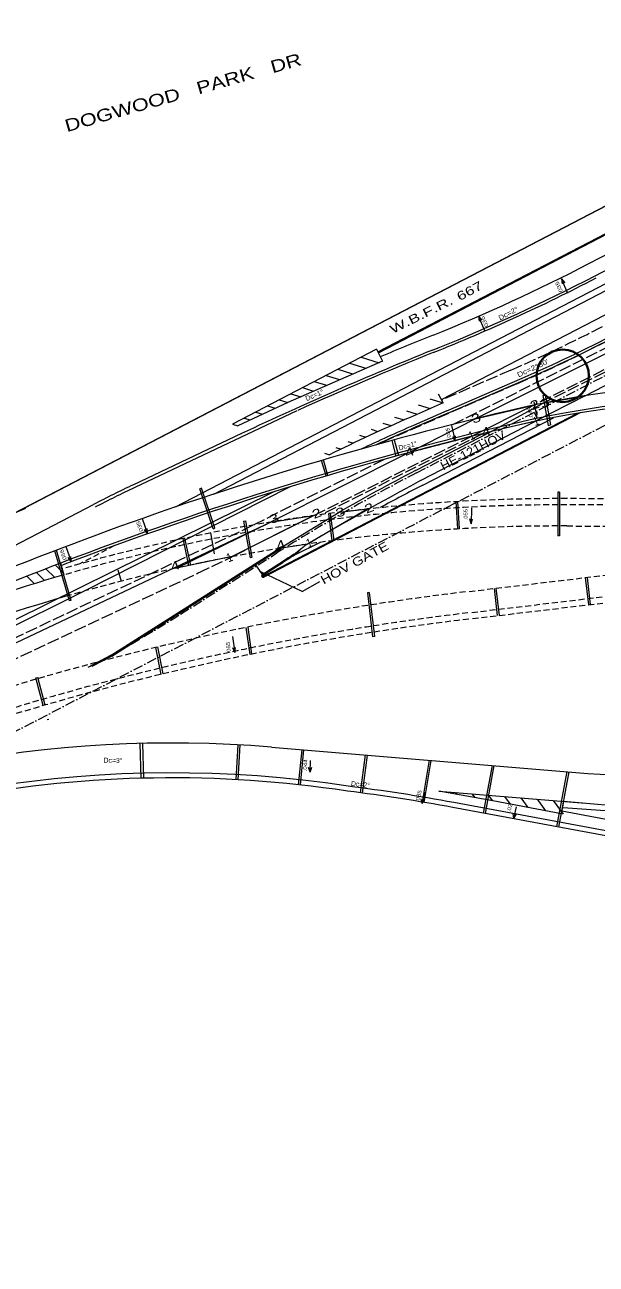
# Model space of a CAD drawing. Extents: x 2354993 to 2372084, y 6966390 to 6990057.
# Drawn here: x 2362087 to 2363006, y 6976825 to 6978818 of the extents above; entities that cross this region are included whole.
import ezdxf
from ezdxf.enums import TextEntityAlignment as Align

# ---------------------------------------------------------------- set-up
doc = ezdxf.new("R2010")
doc.units = 0
doc.header["$LTSCALE"] = 3.2
for name, pattern in [('DOT_DASHED', [7.7, 5, -1.2, 0.3, -1.2]), ('LONG_DASHED', [7.5, 6, -1.5]), ('MEDIUM_DASHED', [4.5, 3, -1.5])]:
    doc.linetypes.add(name, pattern=pattern)
for name, color, linetype, lineweight in [('1', 7, 'Continuous', 35), ('12', 7, 'Continuous', 13), ('13', 7, 'Continuous', 13), ('17', 7, 'Continuous', 13), ('19', 7, 'Continuous', 13), ('25', 7, 'Continuous', 13), ('4', 7, 'Continuous', 13), ('5', 7, 'Continuous', 13), ('6', 7, 'Continuous', 13), ('61', 7, 'Continuous', 13), ('63', 7, 'Continuous', 13), ('9', 7, 'Continuous', 13)]:
    doc.layers.add(name, color=color, linetype=linetype, lineweight=lineweight)

msp = doc.modelspace()

# ---------------------------------------------------------------- linework, layer by layer
at = {"layer": '1', "lineweight": 40}
msp.add_circle((2362951.982, 6978253.986), 42.179, dxfattribs=at)
at = {"layer": '12'}
for p, q in [((2362571.803, 6978092.884), (2362564.446, 6978117.821)), ((2362574.682, 6978093.733), (2362567.324, 6978118.67)), ((2362371.377, 6978073.296), (2362368.532, 6978072.348)), ((2362390.025, 6978007.891), (2362368.532, 6978072.348)), ((2362392.719, 6978009.291), (2362371.377, 6978073.296)), ((2362946.885, 6978066.796), (2362943.878, 6978066.795)), ((2362943.885, 6978066.795), (2362943.935, 6977996.56)), ((2362946.885, 6978066.796), (2362946.934, 6977996.561)), ((2362780.042, 6978051.58), (2362782.606, 6978007.655)), ((2362783.038, 6978051.756), (2362785.602, 6978007.831)), ((2362439.038, 6978020.407), (2362441.991, 6978020.93)), ((2362439.038, 6978020.407), (2362449.499, 6977961.336)), ((2362441.991, 6978020.93), (2362452.451, 6977961.859)), ((2362575.239, 6978032.315), (2362580.866, 6977988.676)), ((2362578.214, 6978032.698), (2362583.841, 6977989.06)), ((2362389.745, 6978018.211), (2362386.9, 6978017.263)), ((2362341.312, 6977992.101), (2362350.49, 6977949.069)), ((2362344.245, 6977992.726), (2362353.424, 6977949.694)), ((2362946.949, 6977996.561), (2362943.935, 6977996.56)), ((2362159.001, 6977891.989), (2362135.767, 6977972.726)), ((2362161.883, 6977892.818), (2362138.577, 6977973.802)), ((2362452.451, 6977961.859), (2362449.499, 6977961.336)), ((2362161.883, 6977892.818), (2362159.001, 6977891.989)), ((2362105.187, 6977768.143), (2362108.085, 6977768.92)), ((2362117.11, 6977723.657), (2362105.187, 6977768.143)), ((2362119.992, 6977724.493), (2362108.085, 6977768.92)), ((2362126.194, 6977701.35), (2362123.296, 6977700.573)), ((2362272.444, 6977662.559), (2362274.102, 6977606.792)), ((2362276.443, 6977662.678), (2362278.1, 6977606.896))]:
    msp.add_line(p, q, dxfattribs=at)
for points in [[(2362640.897, 6977905.496), (2362637.913, 6977905.14), (2362646.394, 6977834.183)], [(2362640.897, 6977905.496), (2362649.372, 6977834.54), (2362646.391, 6977834.183)]]:
    msp.add_lwpolyline(points, dxfattribs=at)
at = {"layer": '17'}
for p, q in [((2362919.834, 6978222.065), (2362923.771, 6978222.772)), ((2362919.834, 6978222.065), (2362928.413, 6978174.288)), ((2362923.771, 6978222.772), (2362932.35, 6978174.995)), ((2362928.413, 6978174.288), (2362932.35, 6978174.995)), ((2362677.146, 6978149.827), (2362683.958, 6978124.875)), ((2362681.005, 6978150.881), (2362687.817, 6978125.928)), ((2361706.685, 6977651.285), (2362482.125, 6978018.666)), ((2362546.028, 6977616.636), (2362543.26, 6977624.219)), ((2362546.028, 6977616.636), (2362546.795, 6977635.37)), ((2362546.028, 6977616.636), (2362548.839, 6977624.427)), ((2362726.084, 6977566.046), (2362730.092, 6977584.363)), ((2362726.084, 6977566.046), (2362724.675, 6977573.994)), ((2362726.084, 6977566.046), (2362730.206, 6977573.23)), ((2362873.476, 6977542.3), (2362872.067, 6977550.248)), ((2362873.476, 6977542.299), (2362877.484, 6977560.616)), ((2362873.476, 6977542.3), (2362877.598, 6977549.484))]:
    msp.add_line(p, q, dxfattribs=at)
at = {"layer": '19'}
for p, q in [((2362949.899, 6978409.967), (2362951.045, 6978401.741)), ((2362949.899, 6978409.967), (2362955.212, 6978403.576)), ((2362960.316, 6978386.382), (2362949.899, 6978409.967)), ((2362816.435, 6978349.953), (2362817.581, 6978341.727)), ((2362816.435, 6978349.953), (2362821.748, 6978343.562)), ((2362826.852, 6978326.368), (2362816.435, 6978349.953)), ((2362905.52, 6978212.363), (2362910.407, 6978187.048)), ((2362910.407, 6978187.048), (2362906.655, 6978194.465)), ((2362910.407, 6978187.048), (2362911.126, 6978195.322)), ((2362779.224, 6978148.867), (2362775.199, 6978155.884)), ((2362804.585, 6978016.032), (2362802.457, 6978024.066)), ((2362284.473, 6977999.932), (2362279.726, 6978006.753)), ((2362161.719, 6977955.18), (2362156.972, 6977962.001)), ((2362424.912, 6977809.025), (2362421.526, 6977816.614))]:
    msp.add_line(p, q, dxfattribs=at)
for points in [[(2362773.018, 6978173.891), (2362779.224, 6978148.867), (2362779.509, 6978157.168)], [(2362805.067, 6978041.81), (2362804.585, 6978016.032), (2362807.009, 6978023.976)], [(2362276.11, 6978024.32), (2362284.473, 6977999.932), (2362284.034, 6978008.226)], [(2362153.356, 6977979.568), (2362161.719, 6977955.18), (2362161.28, 6977963.474)], [(2362421.264, 6977834.548), (2362424.912, 6977809.025), (2362426.034, 6977817.254)]]:
    msp.add_lwpolyline(points, dxfattribs=at)
at = {"layer": '25'}
for p, q in [((2358006.591, 6975920.846), (2363488.891, 6978770.331)), ((2362811.106, 6978184.667), (2363604.71, 6978582.7)), ((2363003.914, 6978414.83), (2363230.047, 6978532.352)), ((2362988.207, 6978222.005), (2363089.737, 6978274.358)), ((2362759.919, 6978210.266), (2362752.541, 6978224.463)), ((2362975.243, 6978193.546), (2362580.871, 6977988.675)), ((2362980.038, 6978194.347), (2362692.88, 6978045.172)), ((2362723.338, 6978085.426), (2362908.292, 6978180.797)), ((2362704.108, 6978130.197), (2362482.125, 6978018.666)), ((2362692.88, 6978045.172), (2362471.439, 6977930.136)), ((2362580.871, 6977988.675), (2362470.748, 6977931.467)), ((2362226.42, 6977804.541), (2362490.493, 6977972.46)), ((2362227.174, 6977803.242), (2362491.298, 6977971.194)), ((2362457.957, 6977949.993), (2362468.945, 6977934.464)), ((2362468.945, 6977934.464), (2362501.492, 6977955.16)), ((2362469.73, 6977933.185), (2362502.297, 6977953.894)), ((2362532.928, 6977907.156), (2362465.571, 6977939.397)), ((2362532.928, 6977907.156), (2362561.479, 6977922.997))]:
    msp.add_line(p, q, dxfattribs=at)
at = {"layer": '25', "linetype": 'LONG_DASHED'}
for p, q in [((2362775.435, 6978175.726), (2363601.123, 6978589.851)), ((2363618.55, 6978565.019), (2362905.562, 6978206.794)), ((2363084.717, 6978292.33), (2362920.65, 6978209.898)), ((2362868.725, 6978263.158), (2362757.536, 6978214.854)), ((2362878.281, 6978241.142), (2362652.39, 6978143.01)), ((2362822.936, 6978160.805), (2362564.328, 6978030.873)), ((2362805.354, 6978156.448), (2362420.606, 6977963.184)), ((2362665.112, 6978119.556), (2362455.357, 6978014.169)), ((2361699.088, 6977656.554), (2362455.357, 6978014.169)), ((2361711.836, 6977629.398), (2362366.21, 6977936.92))]:
    msp.add_line(p, q, dxfattribs=at)
at = {"layer": '25', "linetype": 'MEDIUM_DASHED'}
msp.add_line((2362231.704, 6977980.832), (2362174.616, 6977951.163), dxfattribs=at)
at = {"layer": '25', "linetype": 'LONG_DASHED'}
for centre, radius, start, end in [((2361957.93, 6980359.697), 2285.831, 293.48147, 297.64944), ((2361957.927, 6980359.696), 2309.831, 293.48137, 297.6495), ((2361144.348, 6980536.913), 2872.789, 295.17109, 296.37586)]:
    msp.add_arc(centre, radius, start, end, dxfattribs=at)
at = {"layer": '25'}
for centre, radius, start, end in [((2365652.69, 6972668.039), 6158.667, 118.40149, 120.33806), ((2364029.86, 6975551.655), 2850.789, 121.46196, 121.59891), ((2364029.86, 6975551.655), 2868.789, 122.30227, 122.45191), ((2364029.86, 6975551.655), 2867.289, 122.23233, 122.45191), ((2364029.86, 6975551.655), 2848.289, 122.00852, 122.45191), ((2364029.86, 6975551.655), 2846.789, 122.01179, 122.45191), ((2362470.287, 6977932.355), 2.5, 122.45143, 297.45154), ((2362470.287, 6977932.355), 1, 122.45143, 297.45154)]:
    msp.add_arc(centre, radius, start, end, dxfattribs=at)
at = {"layer": '4'}
for p, q in [((2362757.154, 6978215.587), (2363268.695, 6978481.438)), ((2362385.833, 6978001.212), (2362391.796, 6977967.815)), ((2362520.138, 6977966.916), (2362536.133, 6977979.777)), ((2362520.795, 6977965.558), (2362536.133, 6977979.777)), ((2362242.862, 6977923.152), (2362237.538, 6977941.259))]:
    msp.add_line(p, q, dxfattribs=at)
at = {"layer": '5'}
for p, q in [((2362087.371, 6978041.876), (2363419.143, 6978734.078)), ((2362654.988, 6978292.473), (2363507.292, 6978735.395)), ((2362655.626, 6978291.114), (2363508.018, 6978734.082)), ((2362391.142, 6978063.692), (2363583.984, 6978683.611)), ((2362993.757, 6978434.346), (2363229.499, 6978556.861)), ((2362329.78, 6978043.07), (2363248.405, 6978520.479)), ((2362742.392, 6978295.091), (2362751.833, 6978298.893)), ((2362652.848, 6978297.032), (2362421.419, 6978176.314)), ((2362627.951, 6978284.047), (2362656.76, 6978274.985)), ((2362652.848, 6978297.032), (2362662.138, 6978277.243)), ((2362590.336, 6978264.425), (2362614.259, 6978256.904)), ((2362609.144, 6978274.236), (2362635.439, 6978265.969)), ((2362552.719, 6978244.803), (2362572.28, 6978238.654)), ((2362571.528, 6978254.614), (2362593.203, 6978247.8)), ((2362765.497, 6978197.425), (2362886.96, 6978250.192)), ((2362767.091, 6978193.757), (2362888.554, 6978246.524)), ((2362515.102, 6978225.182), (2362530.824, 6978220.239)), ((2362533.911, 6978234.992), (2362551.488, 6978229.467)), ((2362477.487, 6978205.559), (2362489.88, 6978201.664)), ((2362496.294, 6978215.371), (2362510.289, 6978210.971)), ((2362759.919, 6978210.266), (2362706.512, 6978187.064)), ((2362719.45, 6978207.266), (2362738.922, 6978201.144)), ((2362738.3, 6978217.063), (2362759.919, 6978210.266)), ((2362524.395, 6978197.427), (2362264.183, 6978074.352)), ((2362439.869, 6978185.939), (2362449.429, 6978182.933)), ((2362458.678, 6978195.749), (2362469.594, 6978192.317)), ((2362681.747, 6978187.672), (2362696.925, 6978182.899)), ((2362700.597, 6978197.468), (2362717.922, 6978192.021)), ((2362765.497, 6978197.425), (2362712.091, 6978174.224)), ((2362767.091, 6978193.756), (2362713.852, 6978170.627)), ((2362727.004, 6978078.316), (2362937.068, 6978186.635)), ((2362435.758, 6978161.035), (2362262.045, 6978078.872)), ((2362421.419, 6978176.314), (2362429.768, 6978173.689)), ((2362435.377, 6978160.855), (2362435.764, 6978161.038)), ((2362644.044, 6978168.078), (2362654.929, 6978164.655)), ((2362662.895, 6978177.874), (2362675.926, 6978173.777)), ((2362715.089, 6978101.424), (2362836.859, 6978164.214)), ((2362437.088, 6978157.239), (2362437.474, 6978157.422)), ((2362606.34, 6978148.483), (2362615.458, 6978145.615)), ((2362625.192, 6978158.28), (2362635.464, 6978155.051)), ((2362568.958, 6978129.604), (2362577.161, 6978127.026)), ((2362587.489, 6978138.686), (2362595.692, 6978136.108)), ((2362512.875, 6978075.151), (2362183.72, 6977908.026)), ((2361730.202, 6977803.996), (2362197.968, 6978047.082)), ((2361950.212, 6977982.331), (2362088.839, 6978040.867)), ((2362562.03, 6977986.161), (2362520.795, 6977965.558)), ((2362121.255, 6977943.555), (2362135.481, 6977929.599)), ((2362136.625, 6977949.49), (2362149.095, 6977937.256)), ((2362144.684, 6977952.584), (2362150.078, 6977933.84)), ((2362090.63, 6977931.574), (2362102.673, 6977919.759)), ((2362105.924, 6977937.584), (2362119.037, 6977924.719)), ((2362183.72, 6977908.026), (2361804.561, 6977720.528)), ((2362226.42, 6977804.541), (2362188.485, 6977784.834)), ((2362227.178, 6977803.244), (2362195.267, 6977786.667)), ((2362483.973, 6977656.862), (2362992.478, 6977614.561)), ((2362752.746, 6977586.338), (2362988.499, 6977566.726)), ((2362782.547, 6977580.921), (2362780.307, 6977584.045)), ((2362810.95, 6977575.633), (2362806.479, 6977581.868)), ((2363437.708, 6977444.706), (2362776.995, 6977567.714)), ((2362839.354, 6977570.345), (2362832.652, 6977579.691)), ((2362867.758, 6977565.057), (2362858.825, 6977577.513)), ((2362896.161, 6977559.769), (2362884.997, 6977575.336)), ((2362924.565, 6977554.481), (2362911.17, 6977573.159)), ((2362952.969, 6977549.193), (2362937.343, 6977570.982)), ((2362949.929, 6977549.759), (2362953.59, 6977569.421)), ((2363056.715, 6977560.454), (2362953.628, 6977569.627)), ((2363436.244, 6977436.841), (2362775.531, 6977559.85)), ((2363441.003, 6977462.402), (2362950.662, 6977553.691)), ((2362952.814, 6977559.66), (2363056.326, 6977552.462))]:
    msp.add_line(p, q, dxfattribs=at)
at = {"layer": '5', "linetype": 'MEDIUM_DASHED'}
for p, q in [((2363836.954, 6978043.529), (2362958.726, 6978046.492)), ((2363881.241, 6978053.379), (2362958.761, 6978056.492)), ((2362958.612, 6978012.492), (2363716.295, 6978009.935)), ((2362801.702, 6977907.216), (2363080.587, 6977940.529)), ((2362805.732, 6977873.455), (2363090.394, 6977907.458)), ((2362806.918, 6977863.526), (2363091.58, 6977897.529))]:
    msp.add_line(p, q, dxfattribs=at)
at = {"layer": '5'}
for points in [[(2362662.138, 6978277.243), (2362510.289, 6978210.971), (2362429.768, 6978173.689)], [(2362488.793, 6978067.704), (2362331.734, 6977990.029), (2361705.614, 6977680.376)], [(2362949.929, 6977549.759), (2362839.354, 6977570.345), (2362752.746, 6977586.338)]]:
    msp.add_lwpolyline(points, dxfattribs=at)
for centre, radius, start, end in [((2361676.37, 6980969.25), 2856.789, 291.93666, 297.46082), ((2361676.37, 6980969.25), 2882.789, 291.73437, 297.46082), ((2361676.37, 6980969.25), 2878.789, 291.93666, 297.46082), ((2364877.625, 6972993.336), 5737.578, 111.83502, 112.75114), ((2361968.189, 6980365.073), 2305.831, 293.48164, 297.64942), ((2361968.189, 6980365.073), 2309.831, 293.48164, 297.64942), ((2364877.625, 6972993.336), 5715.578, 111.93666, 115.2919), ((2364877.625, 6972993.336), 5711.578, 111.93666, 114.31325), ((2363244.672, 6976597.082), 1645.014, 38.12295, 103.3303), ((2363244.672, 6976597.082), 1623.014, 38.12295, 103.3303), ((2363244.672, 6976597.082), 1619.014, 38.12295, 103.3303), ((2364188.171, 6972614.757), 5737.613, 103.3303, 115.98006), ((2363855.57, 6975542.087), 2883.789, 113.48158, 116.31519), ((2364188.171, 6972614.757), 5715.613, 103.3303, 110.94842), ((2364188.171, 6972614.757), 5711.613, 103.3303, 110.94842), ((2363855.57, 6975542.087), 2869.789, 113.48158, 115.31325), ((2363858.925, 6975534.821), 2873.789, 113.48158, 114.8312), ((2364029.86, 6975551.655), 2868.789, 117.27758, 120.0623), ((2363078.527, 6976352.647), 1909.58, 115.31354, 117.45987), ((2363078.527, 6976352.647), 1904.58, 115.31354, 117.45987), ((2364029.86, 6975551.655), 2842.789, 117.27758, 118.83624), ((2363097.562, 6979328.645), 1717.302, 266.49182, 308.27248), ((2364188.16, 6972614.79), 5715.578, 110.94799, 113.39373), ((2362948.983, 6975157.719), 2888.789, 106.05464, 110.92598), ((2362948.983, 6975157.719), 2854.789, 106.05463, 117.46086), ((2362324.651, 6975741.618), 1921.859, 85.24473, 116.95937), ((2362324.651, 6975741.618), 1865.859, 81.33444, 119.61246), ((2362324.651, 6975741.618), 1873.859, 81.33444, 116.95937), ((2362255.214, 6974765.083), 2842.789, 79.45368, 82.91209), ((2362255.214, 6974765.083), 2850.789, 79.45368, 82.91209)]:
    msp.add_arc(centre, radius, start, end, dxfattribs=at)
at = {"layer": '5', "linetype": 'MEDIUM_DASHED'}
for centre, radius, start, end in [((2362948.983, 6975157.719), 2898.789, 89.80675, 106.05463), ((2362948.983, 6975157.719), 2888.789, 89.80675, 106.05464), ((2362948.983, 6975157.719), 2854.789, 89.80675, 106.05463), ((2363306.843, 6973626.915), 4310, 96.81172, 111.72863), ((2363306.843, 6973626.915), 4276, 96.81172, 116.96246), ((2363306.843, 6973626.915), 4266, 96.81171, 111.74968)]:
    msp.add_arc(centre, radius, start, end, dxfattribs=at)
at = {"layer": '6', "linetype": 'DOT_DASHED'}
for p, q in [((2360272.717, 6976747.357), (2363548.144, 6978448.903)), ((2360272.718, 6976747.358), (2363548.137, 6978448.9)), ((2360272.718, 6976747.358), (2363548.137, 6978448.9)), ((2362716.922, 6978097.869), (2363083.321, 6978286.801)), ((2362337.537, 6977870.457), (2362492.639, 6977969.084))]:
    msp.add_line(p, q, dxfattribs=at)
at = {"layer": '6'}
msp.add_line((2362390.025, 6978007.891), (2362392.719, 6978009.291), dxfattribs=at)
at = {"layer": '6', "linetype": 'DOT_DASHED'}
for centre, radius, start, end in [((2364029.86, 6975551.655), 2864.789, 117.27758, 122.45191), ((2361312.723, 6979482.076), 1909.859, 297.45108, 302.45191)]:
    msp.add_arc(centre, radius, start, end, dxfattribs=at)
at = {"layer": '61'}
for p, q in [((2362993.869, 6977885.857), (2362988.65, 6977929.547)), ((2362996.848, 6977886.213), (2362991.629, 6977929.903)), ((2362841.545, 6977911.976), (2362846.764, 6977868.285)), ((2362844.525, 6977912.332), (2362849.744, 6977868.641)), ((2362442.748, 6977849.407), (2362448.913, 6977805.756)), ((2362445.692, 6977850.009), (2362451.857, 6977806.359)), ((2362306.338, 6977773.932), (2362297.932, 6977817.166)), ((2362309.808, 6977774.767), (2362301.402, 6977818)), ((2362427.265, 6977604.653), (2362430.344, 6977660.569)), ((2362430.26, 6977604.486), (2362433.34, 6977660.401)), ((2362527.512, 6977596.417), (2362532.933, 6977652.789)), ((2362530.494, 6977596.088), (2362535.923, 6977652.54)), ((2362626.951, 6977583.464), (2362635.04, 6977644.295)), ((2362629.925, 6977583.068), (2362638.033, 6977644.046)), ((2362726.321, 6977568.566), (2362737.685, 6977635.756)), ((2362729.279, 6977568.066), (2362740.685, 6977635.507)), ((2362824.628, 6977550.709), (2362838.894, 6977627.337)), ((2362827.577, 6977550.16), (2362841.899, 6977627.087)), ((2362942.551, 6977528.755), (2362959.144, 6977617.883)), ((2362945.5, 6977528.205), (2362962.094, 6977617.334))]:
    msp.add_line(p, q, dxfattribs=at)
at = {"layer": '63'}
for points in [[(2362920.65, 6978209.898), (2362988.208, 6978222.005), (2362908.292, 6978180.797), (2362836.859, 6978164.214)], [(2362811.106, 6978184.667), (2362905.562, 6978206.794), (2362805.354, 6978156.448), (2362704.108, 6978130.197)], [(2362638.461, 6978039.828), (2362541.941, 6977983.34), (2362496.82, 6977976.472), (2362592.765, 6978034.538)]]:
    msp.add_lwpolyline(points, close=True, dxfattribs=at)
for points in [[(2362331.305, 6977944.885), (2362482.125, 6978018.666), (2362552.11, 6978029.211)], [(2362552.11, 6978029.211), (2362420.606, 6977963.184), (2362331.305, 6977944.885)]]:
    msp.add_lwpolyline(points, dxfattribs=at)
at = {"layer": '9'}
msp.add_arc((2360722.521, 6984327.136), 5729.573, 359.50797, 359.50797, dxfattribs=at)

# ---------------------------------------------------------------- texts
at = {"layer": '13', "width": 1.3}
msp.add_text('DOGWOOD   PARK   DR', height=20, rotation=15.972, dxfattribs=at).set_placement((2362344.408, 6978699.867), align=Align.CENTER)
at = {"layer": '13'}
for s, rotation, width, p in [('667', 28.354, 1.4, (2362786.363, 6978373.913)), ('W.B.F.R.', 26.495, 1.45, (2362678.535, 6978321.105)), ('HE-121HOV', 27.223, 1.1, (2362759.896, 6978101.552)), ('HOV GATE', 28.633, 1.25, (2362567.656, 6977918.108))]:
    msp.add_text(s, height=14, rotation=rotation, dxfattribs=dict(at, width=width)).set_placement(p)
at = {"layer": '17'}
for s, height, rotation, width, p in [('Dc=2°', 8, 27.643, 1.15, (2362851.244, 6978342.856)), ("Dc=2°30'", 7.999, 24.802, 1.25, (2362880.913, 6978251.29)), ('.044', 6, 84.81, 1.25, (2362540.087, 6977617.514)), ('.035', 6, 74.81, 1.25, (2362720.383, 6977567.945)), ('.02', 6, 74.81, 1.2, (2362867.687, 6977551.811))]:
    msp.add_text(s, height=height, rotation=rotation, dxfattribs=dict(at, width=width)).set_placement(p)
for s, height, rotation, p in [('Dc=1°', 8, 23.248, (2362540.482, 6978213.224)), ('Dc=1°', 7.999, 15.237, (2362689.189, 6978133.937)), ('Dc=3°', 8, 358.484, (2362213.825, 6977632.036)), ('Dc=2°', 8, 353.484, (2362611.24, 6977594.771))]:
    msp.add_text(s, height=height, rotation=rotation, dxfattribs=at).set_placement(p)
at = {"layer": '19'}
for s, height, rotation, width, p in [('.035', 5.999, 115.33, 1.35, (2362953.65, 6978387.324)), ('.035', 5.999, 115.33, 1.35, (2362834.169, 6978331.502)), ('.048', 5.999, 100.687, 1.25, (2362904.55, 6978184.965)), ('.035', 6, 99.534, 1.2, (2362772.594, 6978152.386)), ('.055', 6, 90.548, 1.15, (2362798.93, 6978021.713)), ('.035', 6, 109.909, 1.3, (2362278.641, 6978001.811)), ('.055', 5.999, 109.007, 1.3, (2362155.721, 6977956.452)), ('.055', 6, 95.052, 1.2, (2362418.423, 6977807.745))]:
    msp.add_text(s, height=height, rotation=rotation, dxfattribs=dict(at, width=width)).set_placement(p)
at = {"layer": '63'}
for s, width, p in [('2', 1.4, (2362909.422, 6978201.03)), ('3', 1.4, (2362925.679, 6978203.606)), ('3', 1.4, (2362815.101, 6978179.293)), ('1', 0.85, (2362911.514, 6978174.623)), ('1', 0.85, (2362807.857, 6978151.437)), ('4', 1.45, (2362831.047, 6978157.403)), ('4', 1.45, (2362708.075, 6978124.878)), ('2', 1.4, (2362559.023, 6978026.309)), ('3', 1.4, (2362597.009, 6978028.241)), ('2', 1.4, (2362643.335, 6978034.822)), ('3', 1.4, (2362490.455, 6978018.097)), ('4', 1.45, (2362501.217, 6977975.586)), ('1', 0.85, (2362546.95, 6977978.648)), ('1', 0.85, (2362418.828, 6977955.462)), ('4', 1.45, (2362331.279, 6977941.784))]:
    msp.add_text(s, height=14, rotation=21.221, dxfattribs=dict(at, width=width)).set_placement(p, align=Align.CENTER)

doc.saveas('drawing.dxf')
